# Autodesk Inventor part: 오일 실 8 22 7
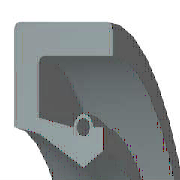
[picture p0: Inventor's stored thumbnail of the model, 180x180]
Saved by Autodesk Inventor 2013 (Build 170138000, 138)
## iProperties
IsCustomPart: 1
Created: 2012-02
Part Number: 오일 실 8 22 7
Material: 고무
Description: 오일-실
Document SubType Name: Modeling
Standard: KS B 2804
Designer: test
Standards Organization: KS
Language: ko-KR
Size Designation: S - 8 22 7
Categories: <MemberInstance><Categories><Category DisplayName="샤프트 부품" InternalName="7f7aeb1f-a693-4053-b835-cee3144e0d98" Mnemonic="SHFT"><Category DisplayName="실링" Intern
Density: 0.93 g/cm^3
Mass: 1.07912 g
Surface Area: 17.6852 cm^2
Volume: 1.16034 cm^3
Author: test
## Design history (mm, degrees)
revolve "본체" stored, may be unused: angle "d17" = 90 deg
revolve "스프링1" stored, may be unused: angle "d18" = 90 deg
body "Solid1"
sketch "스케치1"
  geometry: L1 (0, 11)-(7, 11); L2 (7, 11)-(7, 9.75); L3 (7, 9.75)-(1.75, 9.75); L4 (0, 11)-(0, 6.1); L5 (0, 6.1)-(1.75, 5.75); L6 (1.75, 5.75)-(4.9, 4); L7 (4.9, 4)-(0, 4); L8 (6.3, 4.875)-(6.3, 6.1); L9 (0, 0)-(9.586, 0) reference; L10 (4.9, 4)-(6.3, 4.875); L11 (0, 18)-(0, -3) reference; L12 (-1.917, 0)-(11.503, 0) reference; L13 (4.2, 6.1)-(1.75, 6.59); L14 (1.75, 6.59)-(1.75, 9.75); L15 (6.3, 6.1)-(5.6, 6.1); C1 r 0.455 at (4.9, 6.1); A1 r 0.7 centre (4.9, 6.1) between (5.6, 6.1) and (4.2, 6.1)
  constraints: 26 end point, 5 horizontal alignment, 4 perpendicular, 2 centre point, 2 collinear, 2 horizontal, 2 parallel, 2 point on circle, 2 point on line, 2 vertical alignment, 1 coincident
  dimensions: "d0" = 22 diameter of L1 L9 (= SD2); "d1" = 9.75 diameter of L8.start L9 (= ABDM); "d2" = 1.25 distance of L1.end L2.end (computed from SD); "d3" = 0.91 diameter of C1 (= SPDI); "d4" = 1.4 diameter of A1 (= SPDA); "d5" = 8 diameter of L6.end L9 (= NND); "d6" = 11.5 diameter of L5.end L9 (= TKDM); "d7" = 12.2 diameter of L4.end L9 (= HLDM); "d8" = 4.9 distance from line of C1.centre L4 (= SPDST); "d9" = 6.3 distance between parallel lines of L8 L4 (= SDI); "d10" = 7 distance between parallel lines of L2 L4 (= SWDT); "d12" = 1.75 distance between parallel lines of L14 L4 (= SD)
fillet "모깎기1" dims "d11" = 0.3 (= RR)
other parameters: "SD2" = 22 [user parameter; used in 1 equation term], "SWDT" = 7 [user parameter; used in 1 equation term], "RR" = 0.3 [user parameter; used in 1 equation term], "SD" = 1.75 [user parameter; used in 2 equation terms], "NND" = 8 [user parameter; used in 1 equation term], "SPDA" = 1.4 [user parameter; used in 1 equation term], "SPDI" = 0.91 [user parameter; used in 1 equation term], "TKDM" = 11.5 [user parameter; used in 1 equation term], "HLDM" = 12.2 [user parameter; used in 1 equation term], "ABDM" = 9.75 [user parameter; used in 1 equation term], "SDI" = 6.3 [user parameter; used in 1 equation term], "SPDST" = 4.9 [user parameter; used in 1 equation term], "d13" = 0, "d14" = 0, "d15" = 0, "LAB" = 0.35 [user parameter]
